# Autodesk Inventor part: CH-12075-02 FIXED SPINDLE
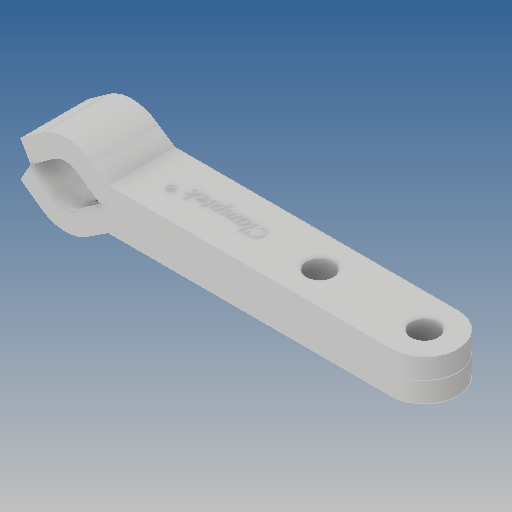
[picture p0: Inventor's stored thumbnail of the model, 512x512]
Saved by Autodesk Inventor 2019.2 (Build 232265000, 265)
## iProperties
Created: 2015-08
Part Number: CH-12075-02 FIXED SPINDLE
Material: Ogólny
Document SubType Name: Modeling
Designer: CADENGINEERING4
Density: 1 g/cm^3
Appearance: Domyślna
Author: CADENGINEERING4
Revision Number: ÈÎºÎ
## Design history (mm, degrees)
feature "ÇÐ³ý-À­Éì2"
feature "ÇÐ³ý-À­Éì5"
node "Bryła1"
node "Bryła2"
